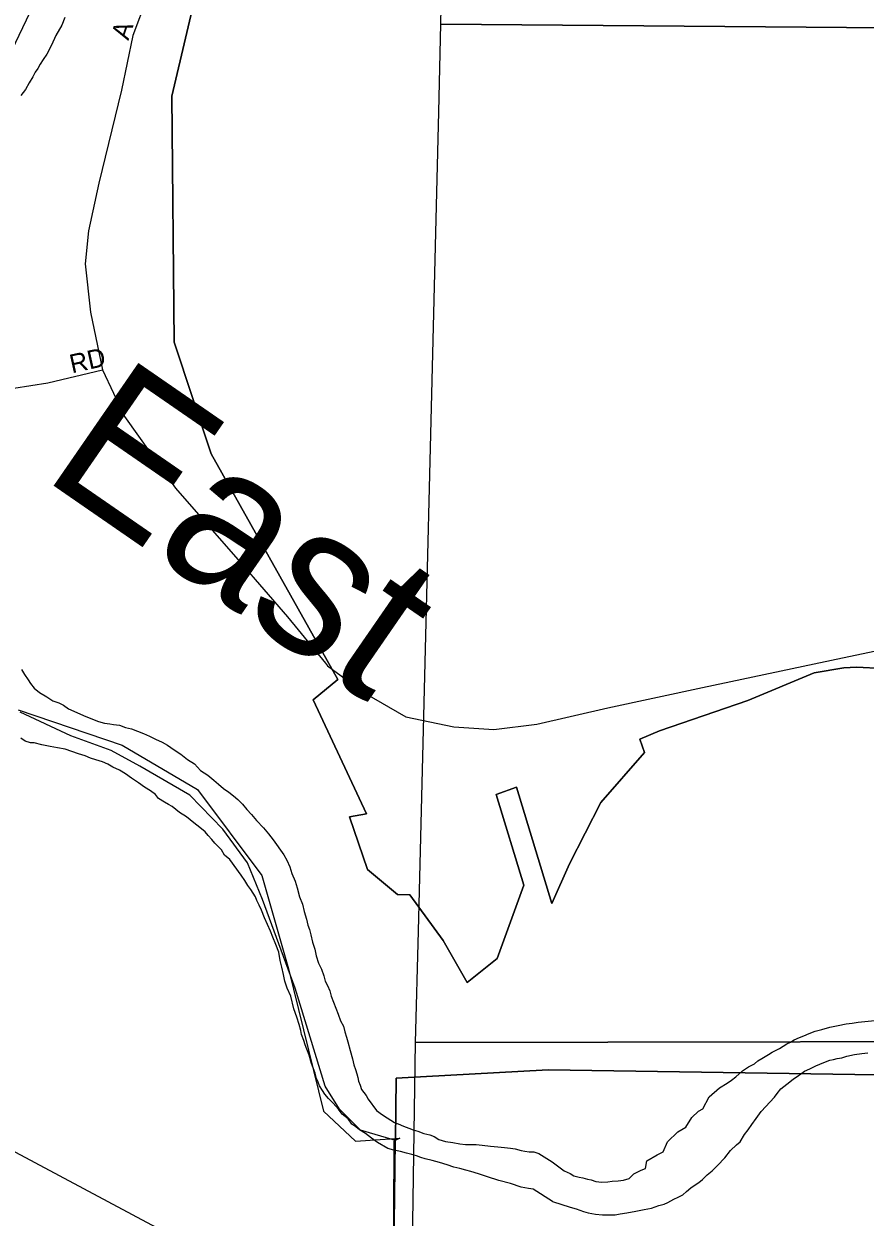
# Model space of a CAD drawing. Extents: x 2010165 to 2382125, y 1060529 to 1407316.
# Drawn here: x 2138681 to 2140939, y 1235186 to 1238386 of the extents above; entities that cross this region are included whole.
import ezdxf

# ---------------------------------------------------------------- set-up
doc = ezdxf.new("R2010")
doc.units = 0
for name, color, linetype in [('GM_X_City_Street', 7, 'Continuous'), ('GM_X_City_Street_Text', 7, 'Continuous'), ('GM_X_Corporation', 7, 'Continuous'), ('GM_X_County_Road', 7, 'Continuous'), ('GM_X_Major_River', 7, 'Continuous'), ('GM_X_Major_River_Text', 7, 'Continuous'), ('GM_X_Section', 7, 'Continuous'), ('GM_X_Township', 7, 'Continuous')]:
    doc.layers.add(name, color=color, linetype=linetype)

msp = doc.modelspace()

# ---------------------------------------------------------------- linework, layer by layer
at = {"layer": 'GM_X_City_Street'}
for points in [[(2139012.4, 1238457.6), (2138973.6, 1238355.1), (2138943.1, 1238208.2), (2138882.2, 1237958.8), (2138854.5, 1237831.4), (2138846.2, 1237742.7), (2138860.1, 1237612.5), (2138892.5, 1237458.4), (2138951.7, 1237333.5), (2139088.4, 1237140.6), (2139261.7, 1236942.8), (2139388.7, 1236796.2), (2139490.5, 1236671.3)], [(2138345, 1237838.5), (2138349.5, 1237833.8), (2138461.1, 1237715.8), (2138481.5, 1237679.7), (2138495.7, 1237641.9), (2138505.1, 1237582.1), (2138531.9, 1237517.6), (2138558.6, 1237472), (2138580.6, 1237440.6), (2138610.5, 1237418.6), (2138654.5, 1237409.1), (2138745.7, 1237423.3), (2138892.5, 1237458.4)], [(2139490.5, 1236671.3), (2139496.1, 1236664.4), (2139596.2, 1236591.1), (2139706.1, 1236527.6), (2139835.5, 1236500.7), (2139942.9, 1236493.4), (2140057.7, 1236508.1), (2140248.1, 1236552), (2140502.4, 1236606), (2140878.5, 1236685.7), (2140984.3, 1236707.9)]]:
    msp.add_lwpolyline(points, dxfattribs=at)
at = {"layer": 'GM_X_Corporation'}
for points in [[(2139159.2, 1238534.3), (2139078.6, 1238192.5), (2139084.3, 1237532), (2139184.2, 1237232.5), (2139523.8, 1236628), (2139458, 1236572.7), (2139600.4, 1236267.3), (2139555.1, 1236259.3), (2139603.6, 1236118.4), (2139684, 1236050.9), (2139717, 1236050.3), (2139806.4, 1235927.4), (2139871.4, 1235814.8), (2139951.4, 1235879.6), (2140022.9, 1236076), (2139948.6, 1236318.9), (2140003.1, 1236338.7), (2140098.4, 1236027), (2140145.6, 1236133), (2140229.6, 1236297.8), (2140346.4, 1236432.1), (2140334.1, 1236467.9), (2140387.4, 1236489.6), (2140623.8, 1236571.5), (2140802.4, 1236645.9), (2140881.5, 1236659.4), (2140915.9, 1236660.8), (2140986.6, 1236657.1)], [(2140986.6, 1236657.1), (2140915.9, 1236660.8), (2140881.5, 1236659.4), (2140802.4, 1236645.9), (2140623.8, 1236571.5), (2140387.4, 1236489.6), (2140334.1, 1236467.9), (2140346.4, 1236432.1), (2140229.6, 1236297.8), (2140145.6, 1236133), (2140098.4, 1236027), (2140003.1, 1236338.7), (2139948.6, 1236318.9), (2140022.9, 1236076), (2139951.4, 1235879.6), (2139871.4, 1235814.8), (2139806.4, 1235927.4), (2139717, 1236050.3), (2139684, 1236050.9), (2139603.6, 1236118.4), (2139555.1, 1236259.3), (2139600.4, 1236267.3), (2139458, 1236572.7), (2139523.8, 1236628), (2139184.2, 1237232.5), (2139084.3, 1237532), (2139078.6, 1238192.5), (2139159.2, 1238534.3)], [(2138630.5, 1238274.9), (2138698, 1238417.6)], [(2144964.8, 1235507), (2140088.5, 1235580.6), (2139680.4, 1235558.3), (2139678.4, 1235391.5), (2139584.8, 1235419.4), (2139528.5, 1235475.3), (2139490.2, 1235537.3), (2139409.1, 1235799.7), (2139322, 1236037.9), (2139281.6, 1236136), (2139215.2, 1236226), (2139126.7, 1236317.8), (2138992.2, 1236395.4), (2138916, 1236437.2), (2138807.7, 1236476.8), (2138671.2, 1236540.3)], [(2139669.9, 1234651.7), (2139678.4, 1235391.5), (2139680.4, 1235558.3), (2140088.5, 1235580.6), (2144964.8, 1235507)]]:
    msp.add_lwpolyline(points, dxfattribs=at)
at = {"layer": 'GM_X_County_Road'}
msp.add_lwpolyline([(2139103.6, 1235122.1), (2138515.1, 1235436), (2138226.9, 1235592.1), (2138164.3, 1235638.9), (2138082.7, 1235752.2), (2137988.9, 1235888.2), (2137666.2, 1236244.8), (2137459.9, 1236424.9), (2137334.7, 1236498.5), (2137228.1, 1236648.7), (2137129.6, 1236783.3), (2137057.4, 1236905.4), (2137033.5, 1236979.2), (2137032.2, 1236985.7), (2137007.1, 1237122.6), (2136985.1, 1237217), (2136933.5, 1237215.5), (2136839.3, 1237209.6), (2136727.3, 1237215.5), (2136605, 1237222.9), (2136475.4, 1237219.9), (2135923, 1237202.2), (2135762.4, 1237202.2), (2135468.9, 1237192.2)], dxfattribs=at)
at = {"layer": 'GM_X_Major_River'}
for points in [[(2138791.1, 1238402.9), (2138783.1, 1238382.8), (2138767.1, 1238354.7), (2138755.2, 1238328.6), (2138743.2, 1238304.5), (2138733.2, 1238290.4), (2138725.3, 1238278.3), (2138719.3, 1238266.2), (2138711.3, 1238256.2), (2138705.3, 1238244.1), (2138695.3, 1238228.1), (2138685.4, 1238210), (2138673.4, 1238193.9)], [(2138674.6, 1236654.8), (2138682.7, 1236640.8), (2138692.8, 1236626.7), (2138698.8, 1236616.7), (2138708.9, 1236604.7), (2138723, 1236592.7), (2138743.1, 1236580.8), (2138759.2, 1236570.8), (2138775.3, 1236564.8), (2138787.3, 1236558.8), (2138801.4, 1236548.8), (2138823.5, 1236538.9), (2138841.6, 1236530.9), (2138865.7, 1236520.9), (2138881.8, 1236515), (2138897.9, 1236511), (2138911.9, 1236509), (2138922, 1236507.1), (2138938, 1236505.1), (2138954.1, 1236499.1), (2138970.2, 1236495.2), (2138986.2, 1236489.2), (2139002.3, 1236483.2), (2139018.4, 1236475.3), (2139034.5, 1236467.3), (2139052.6, 1236459.3), (2139066.6, 1236451.3), (2139084.7, 1236439.4), (2139102.8, 1236427.4), (2139120.9, 1236413.4), (2139139, 1236401.4), (2139155.2, 1236383.4), (2139175.3, 1236371.4), (2139191.4, 1236357.4), (2139203.4, 1236347.4), (2139217.5, 1236335.4), (2139231.6, 1236325.4), (2139243.7, 1236315.4), (2139255.8, 1236305.4), (2139267.8, 1236293.4), (2139279.9, 1236279.4), (2139292, 1236265.4), (2139306.1, 1236249.4), (2139324.2, 1236229.4), (2139338.3, 1236213.4), (2139350.4, 1236197.4), (2139378.7, 1236157.3), (2139386.7, 1236143.3), (2139394.8, 1236125.3), (2139400.9, 1236107.2), (2139409, 1236087.2), (2139415.1, 1236069.2), (2139421.2, 1236045.1), (2139429.3, 1236025.1), (2139433.4, 1236005), (2139439.5, 1235985), (2139443.5, 1235968.9), (2139447.6, 1235956.9), (2139451.6, 1235942.9), (2139455.7, 1235922.8), (2139461.8, 1235904.8), (2139465.9, 1235886.7), (2139472, 1235866.7), (2139480.1, 1235850.6), (2139486.1, 1235832.6), (2139490.2, 1235818.6), (2139496.3, 1235806.6), (2139502.3, 1235792.5), (2139506.4, 1235778.5), (2139512.5, 1235762.4), (2139518.5, 1235746.4), (2139524.6, 1235730.4), (2139530.7, 1235712.3), (2139538.8, 1235698.3), (2139542.8, 1235682.3), (2139546.9, 1235668.3), (2139551, 1235656.2), (2139557.1, 1235632.2), (2139563.2, 1235610.1), (2139567.2, 1235594.1), (2139571.3, 1235582.1), (2139575.3, 1235570), (2139577.4, 1235560), (2139579.4, 1235550), (2139583.5, 1235539.9), (2139587.5, 1235527.9)], [(2138827.9, 1236428.5), (2138809.8, 1236434.5), (2138791.8, 1236440.4), (2138771.7, 1236444.4), (2138751.6, 1236448.3), (2138729.5, 1236452.3), (2138709.4, 1236458.2), (2138699.4, 1236458.2), (2138685.3, 1236462.2), (2138673.3, 1236470.2)], [(2140100.3, 1235227.3), (2140048, 1235260.5), (2140035.9, 1235262.4), (2140015.8, 1235266.4), (2139987.7, 1235276.3), (2139955.6, 1235284.3), (2139925.4, 1235294.2), (2139901.3, 1235302.1), (2139881.2, 1235308.1), (2139867.2, 1235312.1), (2139851.1, 1235316), (2139835, 1235320), (2139817, 1235326), (2139796.9, 1235331.9), (2139776.8, 1235337.9), (2139758.7, 1235341.8), (2139746.7, 1235345.8), (2139734.6, 1235349.8), (2139722.6, 1235353.8), (2139708.5, 1235357.7), (2139692.4, 1235361.7), (2139674.4, 1235365.6), (2139658.3, 1235369.6), (2139630.1, 1235385.6), (2139614, 1235397.6), (2139597.9, 1235409.6), (2139581.9, 1235419.5), (2139571.8, 1235427.5), (2139561.7, 1235435.5), (2139551.7, 1235449.5), (2139535.6, 1235461.5), (2139525.5, 1235475.5), (2139511.4, 1235491.6), (2139499.3, 1235503.6), (2139489.2, 1235515.6), (2139483.2, 1235525.6), (2139475.1, 1235537.6), (2139471.1, 1235547.6), (2139467, 1235557.6), (2139463, 1235571.7), (2139452.8, 1235597.7), (2139446.7, 1235619.8), (2139440.7, 1235635.8), (2139436.6, 1235647.8), (2139432.5, 1235659.9), (2139426.5, 1235675.9), (2139424.4, 1235685.9), (2139420.4, 1235702), (2139414.3, 1235722), (2139406.2, 1235744.1), (2139398, 1235778.1), (2139387.9, 1235800.2), (2139381.8, 1235818.2), (2139377.8, 1235836.3), (2139373.7, 1235856.3), (2139369.6, 1235874.4), (2139365.5, 1235896.4), (2139357.4, 1235916.5), (2139349.3, 1235936.5), (2139343.3, 1235952.6), (2139335.2, 1235970.6), (2139327.1, 1235988.6), (2139319, 1236008.7), (2139312.9, 1236022.7), (2139306.9, 1236034.7), (2139302.8, 1236044.7), (2139290.7, 1236064.8), (2139282.6, 1236074.8), (2139274.6, 1236088.8), (2139264.5, 1236102.8), (2139234.2, 1236144.8), (2139220.1, 1236156.8), (2139212.1, 1236170.9), (2139194, 1236188.9), (2139185.9, 1236198.9), (2139175.8, 1236208.9), (2139167.8, 1236218.9), (2139153.7, 1236230.9), (2139137.6, 1236242.9), (2139117.5, 1236258.9), (2139099.4, 1236270.8), (2139079.2, 1236286.8), (2139069.2, 1236292.8), (2139059.1, 1236298.8), (2139043, 1236308.8), (2139035, 1236318.8), (2139020.9, 1236328.8), (2139004.8, 1236338.8), (2138988.7, 1236350.8), (2138970.6, 1236362.7), (2138954.5, 1236374.7), (2138938.4, 1236384.7), (2138920.4, 1236392.7), (2138906.3, 1236400.7), (2138892.2, 1236406.6), (2138874.1, 1236412.6), (2138860.1, 1236416.6), (2138846, 1236422.6), (2138827.9, 1236428.5)], [(2140099.5, 1235334.4), (2140131.1, 1235310.1), (2140147.3, 1235302.4), (2140157.5, 1235296.6), (2140171.6, 1235292.8), (2140181.7, 1235291), (2140193.8, 1235287.2), (2140203.8, 1235285.4), (2140215.9, 1235281.6), (2140232, 1235279.9), (2140248.1, 1235280.2), (2140260.1, 1235282.5), (2140276.1, 1235282.8), (2140290.1, 1235285.1), (2140306.1, 1235289.4), (2140317.9, 1235301.6), (2140337.8, 1235312), (2140349.8, 1235316.3), (2140353.4, 1235336.4), (2140381.2, 1235353), (2140397.1, 1235361.3), (2140408.6, 1235387.6), (2140436.2, 1235414.3), (2140458.1, 1235426.7), (2140473.7, 1235453.1), (2140491.4, 1235469.5), (2140503.3, 1235475.8), (2140520.8, 1235508.2), (2140548.4, 1235532.8), (2140568.3, 1235545.2), (2140580.1, 1235553.5), (2140592, 1235561.8), (2140609.8, 1235578.1), (2140625.7, 1235588.5), (2140641.6, 1235596.8), (2140651.4, 1235605), (2140661.4, 1235611.2), (2140679.2, 1235621.6), (2140689.1, 1235627.8), (2140709, 1235638.2), (2140718.9, 1235644.4), (2140728.9, 1235650.7), (2140738.8, 1235654.9), (2140748.7, 1235661.1), (2140762.7, 1235667.4), (2140774.6, 1235671.6), (2140788.6, 1235677.9), (2140804.5, 1235684.2), (2140822.5, 1235688.6), (2140844.4, 1235695), (2140866.4, 1235699.5), (2140888.4, 1235703.9), (2140904.4, 1235706.2), (2140920.4, 1235708.5), (2140964.5, 1235713.4)], [(2140100.3, 1235227.3), (2140147, 1235212.1), (2140163.1, 1235208.4), (2140173.2, 1235204.5), (2140183.3, 1235200.7), (2140195.5, 1235196.9), (2140215.6, 1235193.3), (2140233.7, 1235191.6), (2140251.7, 1235192), (2140267.8, 1235192.3), (2140281.8, 1235194.6), (2140299.8, 1235196.9), (2140323.8, 1235201.4), (2140345.8, 1235205.8), (2140365.8, 1235210.2), (2140385.7, 1235216.6), (2140399.7, 1235220.9), (2140409.6, 1235225.1), (2140425.5, 1235233.5), (2140437.5, 1235239.7), (2140449.4, 1235245.9), (2140459.3, 1235254.2), (2140471.1, 1235264.4), (2140483, 1235272.7), (2140492.9, 1235278.9), (2140502.8, 1235287.1), (2140514.6, 1235299.4), (2140528.5, 1235309.7), (2140542.3, 1235324), (2140562, 1235344.4), (2140577.6, 1235364.8), (2140593.4, 1235379.2), (2140603.3, 1235387.4), (2140615, 1235407.7), (2140624.8, 1235419.9), (2140634.5, 1235434.1), (2140646.3, 1235450.4), (2140660, 1235468.7), (2140695.4, 1235507.5), (2140703.2, 1235517.7), (2140713, 1235529.9), (2140736.8, 1235548.5), (2140746.6, 1235556.7), (2140756.6, 1235562.9), (2140776.4, 1235577.3), (2140790.3, 1235583.6), (2140806.2, 1235591.9), (2140828.1, 1235600.4), (2140844.1, 1235606.7), (2140854, 1235608.9), (2140864, 1235611.1), (2140876, 1235613.3), (2140890, 1235617.6), (2140910, 1235622), (2140930, 1235624.4), (2140946, 1235626.7)], [(2139587.5, 1235527.9), (2139599.6, 1235511.9), (2139605.7, 1235501.9), (2139627.8, 1235471.9), (2139643.9, 1235459.9), (2139656, 1235451.9), (2139666, 1235445.9), (2139676.1, 1235439.9), (2139686.2, 1235435.9), (2139700.2, 1235429.9), (2139714.3, 1235424), (2139726.3, 1235420), (2139738.4, 1235416), (2139754.5, 1235410.1), (2139770.5, 1235406.1), (2139782.6, 1235402.1), (2139794.6, 1235394.1), (2139812.7, 1235388.2), (2139832.8, 1235386.2), (2139850.9, 1235382.3), (2139866.9, 1235380.3), (2139881, 1235380.3), (2139895, 1235380.4), (2139911.1, 1235378.4), (2139933.2, 1235376.5), (2139953.2, 1235374.6), (2139971.3, 1235372.6), (2139987.4, 1235370.6), (2139999.4, 1235368.7), (2140015.5, 1235364.7), (2140025.5, 1235362.8), (2140037.6, 1235360.8), (2140049.6, 1235360.8), (2140063.7, 1235356.8), (2140099.5, 1235334.4)]]:
    msp.add_lwpolyline(points, dxfattribs=at)
at = {"layer": 'GM_X_Section'}
for points in [[(2141922.4, 1241143.5), (2141869.6, 1238367.9), (2139800.3, 1238385.2), (2139842.1, 1240542.5), (2139854.6, 1241162.3)], [(2141869.6, 1238367.9), (2141797.8, 1235658.1), (2139732.4, 1235654), (2139740.6, 1235952.8), (2139795.1, 1238150), (2139800.3, 1238385.2)], [(2139732.4, 1235654), (2141797.8, 1235658.1), (2141720.3, 1232890.9), (2139704.7, 1232886.4), (2139705.7, 1233846.9)]]:
    msp.add_lwpolyline(points, close=True, dxfattribs=at)
at = {"layer": 'GM_X_Township'}
msp.add_lwpolyline([(2138666.4, 1236545.9), (2138945, 1236451.5), (2139147.4, 1236333), (2139319.7, 1236102.2), (2139391.6, 1235851.4), (2139485.5, 1235470.2), (2139571.6, 1235389.9), (2139689.9, 1235397.8), (2139673.9, 1235389.8), (2139671.7, 1234782.4)], dxfattribs=at)

# ---------------------------------------------------------------- texts
at = {"layer": 'GM_X_City_Street_Text'}
for s, rotation, p in [('A', 71.4752, (2138961.8, 1238340.1)), ('RD', 12.5224, (2138810.3, 1237448.7))]:
    msp.add_text(s, height=50, rotation=rotation, dxfattribs=at).set_placement(p)
at = {"layer": 'GM_X_Major_River_Text'}
msp.add_text('East', height=400.24, rotation=325.3782, dxfattribs=at).set_placement((2138725.1, 1237172.3))

doc.saveas('drawing.dxf')
